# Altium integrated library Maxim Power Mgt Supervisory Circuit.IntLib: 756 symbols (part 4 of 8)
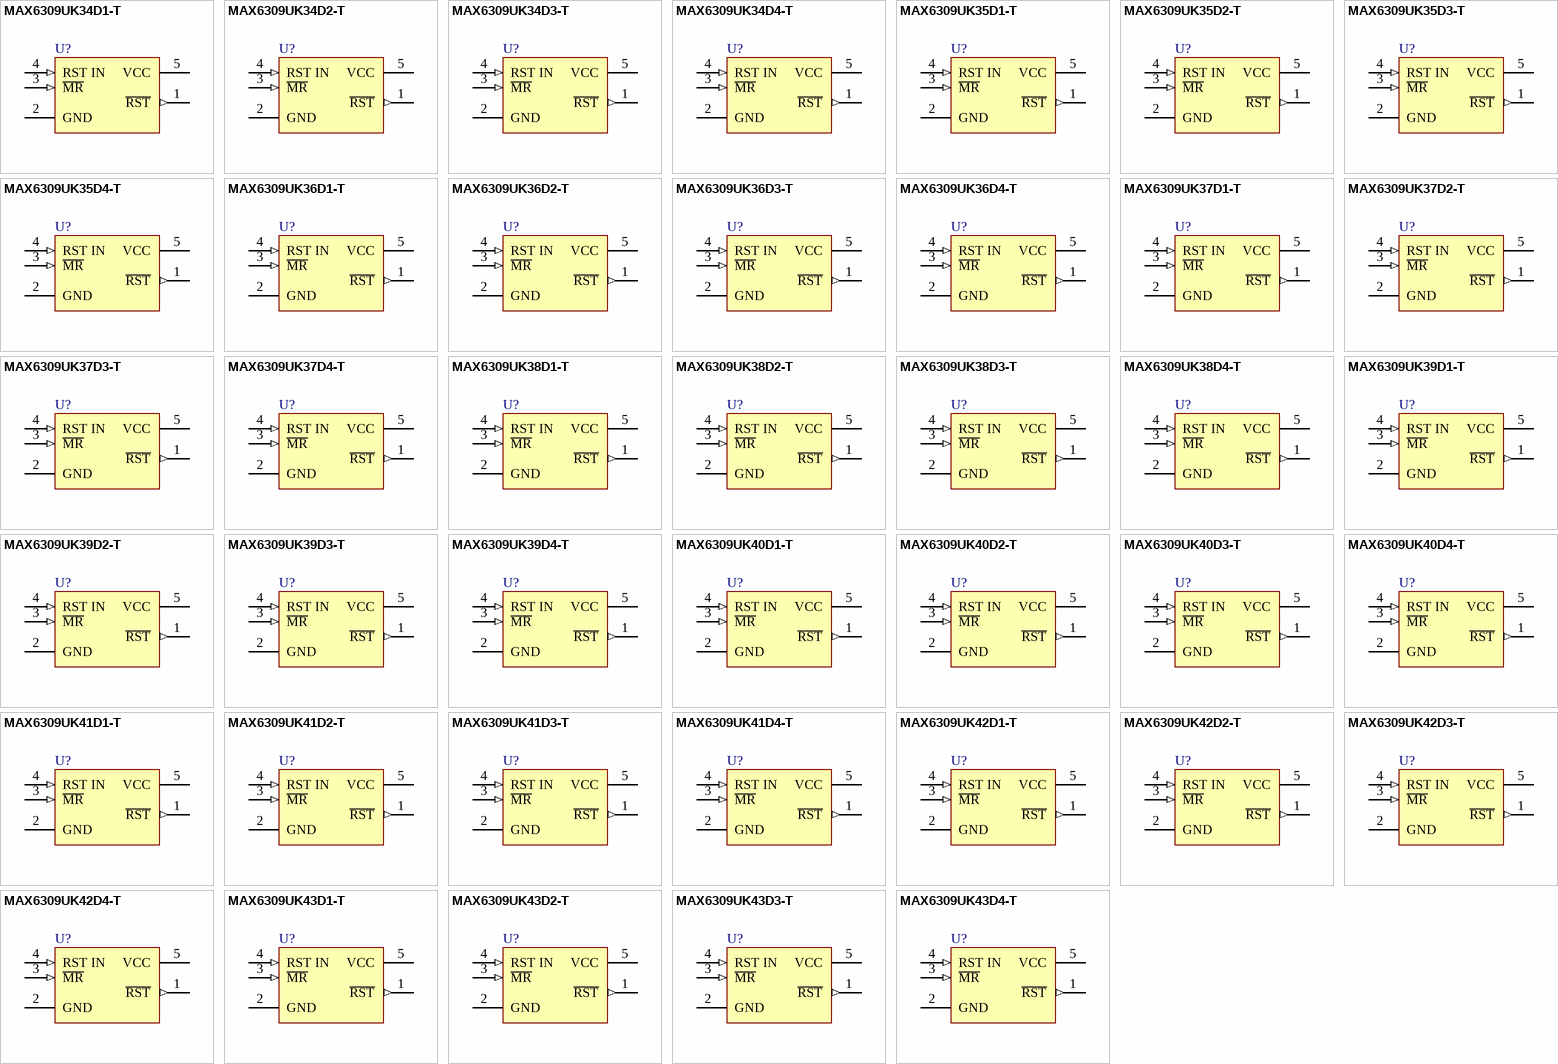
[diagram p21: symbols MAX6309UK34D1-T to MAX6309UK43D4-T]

## MAX6309UK35D2-T
designator U?
5-Pin, Multiple-Input, Programmable Reset IC
footprint SOT23-5_N (SOT23, 5-Leads, Body 2.9x1.6mm, Pitch 0.95mm, Lead Span 2.8mm, IPC Medium Density)
footprint SOT23-5_L (SOT23, 5-Leads, Body 2.9x1.6mm, Pitch 0.95mm, Lead Span 2.8mm, IPC High Density)
footprint SOT23-5_M (SOT23, 5-Leads, Body 2.9x1.6mm, Pitch 0.95mm, Lead Span 2.8mm, IPC Low Density)
pins: 1 ~{RST} (out), 2 GND (power), 3 ~{MR} (in), 4 RST IN (in), 5 VCC (power)

## MAX6309UK35D3-T
designator U?
5-Pin, Multiple-Input, Programmable Reset IC
footprint SOT23-5_N (SOT23, 5-Leads, Body 2.9x1.6mm, Pitch 0.95mm, Lead Span 2.8mm, IPC Medium Density)
footprint SOT23-5_L (SOT23, 5-Leads, Body 2.9x1.6mm, Pitch 0.95mm, Lead Span 2.8mm, IPC High Density)
footprint SOT23-5_M (SOT23, 5-Leads, Body 2.9x1.6mm, Pitch 0.95mm, Lead Span 2.8mm, IPC Low Density)
pins: 1 ~{RST} (out), 2 GND (power), 3 ~{MR} (in), 4 RST IN (in), 5 VCC (power)

## MAX6309UK35D4-T
designator U?
5-Pin, Multiple-Input, Programmable Reset IC
footprint SOT23-5_N (SOT23, 5-Leads, Body 2.9x1.6mm, Pitch 0.95mm, Lead Span 2.8mm, IPC Medium Density)
footprint SOT23-5_L (SOT23, 5-Leads, Body 2.9x1.6mm, Pitch 0.95mm, Lead Span 2.8mm, IPC High Density)
footprint SOT23-5_M (SOT23, 5-Leads, Body 2.9x1.6mm, Pitch 0.95mm, Lead Span 2.8mm, IPC Low Density)
pins: 1 ~{RST} (out), 2 GND (power), 3 ~{MR} (in), 4 RST IN (in), 5 VCC (power)

## MAX6309UK36D1-T
designator U?
5-Pin, Multiple-Input, Programmable Reset IC
footprint SOT23-5_N (SOT23, 5-Leads, Body 2.9x1.6mm, Pitch 0.95mm, Lead Span 2.8mm, IPC Medium Density)
footprint SOT23-5_L (SOT23, 5-Leads, Body 2.9x1.6mm, Pitch 0.95mm, Lead Span 2.8mm, IPC High Density)
footprint SOT23-5_M (SOT23, 5-Leads, Body 2.9x1.6mm, Pitch 0.95mm, Lead Span 2.8mm, IPC Low Density)
pins: 1 ~{RST} (out), 2 GND (power), 3 ~{MR} (in), 4 RST IN (in), 5 VCC (power)

## MAX6309UK36D2-T
designator U?
5-Pin, Multiple-Input, Programmable Reset IC
footprint SOT23-5_N (SOT23, 5-Leads, Body 2.9x1.6mm, Pitch 0.95mm, Lead Span 2.8mm, IPC Medium Density)
footprint SOT23-5_L (SOT23, 5-Leads, Body 2.9x1.6mm, Pitch 0.95mm, Lead Span 2.8mm, IPC High Density)
footprint SOT23-5_M (SOT23, 5-Leads, Body 2.9x1.6mm, Pitch 0.95mm, Lead Span 2.8mm, IPC Low Density)
pins: 1 ~{RST} (out), 2 GND (power), 3 ~{MR} (in), 4 RST IN (in), 5 VCC (power)

## MAX6309UK36D3-T
designator U?
5-Pin, Multiple-Input, Programmable Reset IC
footprint SOT23-5_N (SOT23, 5-Leads, Body 2.9x1.6mm, Pitch 0.95mm, Lead Span 2.8mm, IPC Medium Density)
footprint SOT23-5_L (SOT23, 5-Leads, Body 2.9x1.6mm, Pitch 0.95mm, Lead Span 2.8mm, IPC High Density)
footprint SOT23-5_M (SOT23, 5-Leads, Body 2.9x1.6mm, Pitch 0.95mm, Lead Span 2.8mm, IPC Low Density)
pins: 1 ~{RST} (out), 2 GND (power), 3 ~{MR} (in), 4 RST IN (in), 5 VCC (power)

## MAX6309UK36D4-T
designator U?
5-Pin, Multiple-Input, Programmable Reset IC
footprint SOT23-5_N (SOT23, 5-Leads, Body 2.9x1.6mm, Pitch 0.95mm, Lead Span 2.8mm, IPC Medium Density)
footprint SOT23-5_L (SOT23, 5-Leads, Body 2.9x1.6mm, Pitch 0.95mm, Lead Span 2.8mm, IPC High Density)
footprint SOT23-5_M (SOT23, 5-Leads, Body 2.9x1.6mm, Pitch 0.95mm, Lead Span 2.8mm, IPC Low Density)
pins: 1 ~{RST} (out), 2 GND (power), 3 ~{MR} (in), 4 RST IN (in), 5 VCC (power)

## MAX6309UK37D1-T
designator U?
5-Pin, Multiple-Input, Programmable Reset IC
footprint SOT23-5_N (SOT23, 5-Leads, Body 2.9x1.6mm, Pitch 0.95mm, Lead Span 2.8mm, IPC Medium Density)
footprint SOT23-5_L (SOT23, 5-Leads, Body 2.9x1.6mm, Pitch 0.95mm, Lead Span 2.8mm, IPC High Density)
footprint SOT23-5_M (SOT23, 5-Leads, Body 2.9x1.6mm, Pitch 0.95mm, Lead Span 2.8mm, IPC Low Density)
pins: 1 ~{RST} (out), 2 GND (power), 3 ~{MR} (in), 4 RST IN (in), 5 VCC (power)

## MAX6309UK37D2-T
designator U?
5-Pin, Multiple-Input, Programmable Reset IC
footprint SOT23-5_N (SOT23, 5-Leads, Body 2.9x1.6mm, Pitch 0.95mm, Lead Span 2.8mm, IPC Medium Density)
footprint SOT23-5_L (SOT23, 5-Leads, Body 2.9x1.6mm, Pitch 0.95mm, Lead Span 2.8mm, IPC High Density)
footprint SOT23-5_M (SOT23, 5-Leads, Body 2.9x1.6mm, Pitch 0.95mm, Lead Span 2.8mm, IPC Low Density)
pins: 1 ~{RST} (out), 2 GND (power), 3 ~{MR} (in), 4 RST IN (in), 5 VCC (power)

## MAX6309UK37D3-T
designator U?
5-Pin, Multiple-Input, Programmable Reset IC
footprint SOT23-5_N (SOT23, 5-Leads, Body 2.9x1.6mm, Pitch 0.95mm, Lead Span 2.8mm, IPC Medium Density)
footprint SOT23-5_L (SOT23, 5-Leads, Body 2.9x1.6mm, Pitch 0.95mm, Lead Span 2.8mm, IPC High Density)
footprint SOT23-5_M (SOT23, 5-Leads, Body 2.9x1.6mm, Pitch 0.95mm, Lead Span 2.8mm, IPC Low Density)
pins: 1 ~{RST} (out), 2 GND (power), 3 ~{MR} (in), 4 RST IN (in), 5 VCC (power)

## MAX6309UK37D4-T
designator U?
5-Pin, Multiple-Input, Programmable Reset IC
footprint SOT23-5_N (SOT23, 5-Leads, Body 2.9x1.6mm, Pitch 0.95mm, Lead Span 2.8mm, IPC Medium Density)
footprint SOT23-5_L (SOT23, 5-Leads, Body 2.9x1.6mm, Pitch 0.95mm, Lead Span 2.8mm, IPC High Density)
footprint SOT23-5_M (SOT23, 5-Leads, Body 2.9x1.6mm, Pitch 0.95mm, Lead Span 2.8mm, IPC Low Density)
pins: 1 ~{RST} (out), 2 GND (power), 3 ~{MR} (in), 4 RST IN (in), 5 VCC (power)

## MAX6309UK38D1-T
designator U?
5-Pin, Multiple-Input, Programmable Reset IC
footprint SOT23-5_N (SOT23, 5-Leads, Body 2.9x1.6mm, Pitch 0.95mm, Lead Span 2.8mm, IPC Medium Density)
footprint SOT23-5_L (SOT23, 5-Leads, Body 2.9x1.6mm, Pitch 0.95mm, Lead Span 2.8mm, IPC High Density)
footprint SOT23-5_M (SOT23, 5-Leads, Body 2.9x1.6mm, Pitch 0.95mm, Lead Span 2.8mm, IPC Low Density)
pins: 1 ~{RST} (out), 2 GND (power), 3 ~{MR} (in), 4 RST IN (in), 5 VCC (power)

## MAX6309UK38D2-T
designator U?
5-Pin, Multiple-Input, Programmable Reset IC
footprint SOT23-5_N (SOT23, 5-Leads, Body 2.9x1.6mm, Pitch 0.95mm, Lead Span 2.8mm, IPC Medium Density)
footprint SOT23-5_L (SOT23, 5-Leads, Body 2.9x1.6mm, Pitch 0.95mm, Lead Span 2.8mm, IPC High Density)
footprint SOT23-5_M (SOT23, 5-Leads, Body 2.9x1.6mm, Pitch 0.95mm, Lead Span 2.8mm, IPC Low Density)
pins: 1 ~{RST} (out), 2 GND (power), 3 ~{MR} (in), 4 RST IN (in), 5 VCC (power)

## MAX6309UK38D3-T
designator U?
5-Pin, Multiple-Input, Programmable Reset IC
footprint SOT23-5_N (SOT23, 5-Leads, Body 2.9x1.6mm, Pitch 0.95mm, Lead Span 2.8mm, IPC Medium Density)
footprint SOT23-5_L (SOT23, 5-Leads, Body 2.9x1.6mm, Pitch 0.95mm, Lead Span 2.8mm, IPC High Density)
footprint SOT23-5_M (SOT23, 5-Leads, Body 2.9x1.6mm, Pitch 0.95mm, Lead Span 2.8mm, IPC Low Density)
pins: 1 ~{RST} (out), 2 GND (power), 3 ~{MR} (in), 4 RST IN (in), 5 VCC (power)

## MAX6309UK38D4-T
designator U?
5-Pin, Multiple-Input, Programmable Reset IC
footprint SOT23-5_N (SOT23, 5-Leads, Body 2.9x1.6mm, Pitch 0.95mm, Lead Span 2.8mm, IPC Medium Density)
footprint SOT23-5_L (SOT23, 5-Leads, Body 2.9x1.6mm, Pitch 0.95mm, Lead Span 2.8mm, IPC High Density)
footprint SOT23-5_M (SOT23, 5-Leads, Body 2.9x1.6mm, Pitch 0.95mm, Lead Span 2.8mm, IPC Low Density)
pins: 1 ~{RST} (out), 2 GND (power), 3 ~{MR} (in), 4 RST IN (in), 5 VCC (power)

## MAX6309UK39D1-T
designator U?
5-Pin, Multiple-Input, Programmable Reset IC
footprint SOT23-5_N (SOT23, 5-Leads, Body 2.9x1.6mm, Pitch 0.95mm, Lead Span 2.8mm, IPC Medium Density)
footprint SOT23-5_L (SOT23, 5-Leads, Body 2.9x1.6mm, Pitch 0.95mm, Lead Span 2.8mm, IPC High Density)
footprint SOT23-5_M (SOT23, 5-Leads, Body 2.9x1.6mm, Pitch 0.95mm, Lead Span 2.8mm, IPC Low Density)
pins: 1 ~{RST} (out), 2 GND (power), 3 ~{MR} (in), 4 RST IN (in), 5 VCC (power)

## MAX6309UK39D2-T
designator U?
5-Pin, Multiple-Input, Programmable Reset IC
footprint SOT23-5_N (SOT23, 5-Leads, Body 2.9x1.6mm, Pitch 0.95mm, Lead Span 2.8mm, IPC Medium Density)
footprint SOT23-5_L (SOT23, 5-Leads, Body 2.9x1.6mm, Pitch 0.95mm, Lead Span 2.8mm, IPC High Density)
footprint SOT23-5_M (SOT23, 5-Leads, Body 2.9x1.6mm, Pitch 0.95mm, Lead Span 2.8mm, IPC Low Density)
pins: 1 ~{RST} (out), 2 GND (power), 3 ~{MR} (in), 4 RST IN (in), 5 VCC (power)

## MAX6309UK39D3-T
designator U?
5-Pin, Multiple-Input, Programmable Reset IC
footprint SOT23-5_N (SOT23, 5-Leads, Body 2.9x1.6mm, Pitch 0.95mm, Lead Span 2.8mm, IPC Medium Density)
footprint SOT23-5_L (SOT23, 5-Leads, Body 2.9x1.6mm, Pitch 0.95mm, Lead Span 2.8mm, IPC High Density)
footprint SOT23-5_M (SOT23, 5-Leads, Body 2.9x1.6mm, Pitch 0.95mm, Lead Span 2.8mm, IPC Low Density)
pins: 1 ~{RST} (out), 2 GND (power), 3 ~{MR} (in), 4 RST IN (in), 5 VCC (power)

## MAX6309UK39D4-T
designator U?
5-Pin, Multiple-Input, Programmable Reset IC
footprint SOT23-5_N (SOT23, 5-Leads, Body 2.9x1.6mm, Pitch 0.95mm, Lead Span 2.8mm, IPC Medium Density)
footprint SOT23-5_L (SOT23, 5-Leads, Body 2.9x1.6mm, Pitch 0.95mm, Lead Span 2.8mm, IPC High Density)
footprint SOT23-5_M (SOT23, 5-Leads, Body 2.9x1.6mm, Pitch 0.95mm, Lead Span 2.8mm, IPC Low Density)
pins: 1 ~{RST} (out), 2 GND (power), 3 ~{MR} (in), 4 RST IN (in), 5 VCC (power)

## MAX6309UK40D1-T
designator U?
5-Pin, Multiple-Input, Programmable Reset IC
footprint SOT23-5_N (SOT23, 5-Leads, Body 2.9x1.6mm, Pitch 0.95mm, Lead Span 2.8mm, IPC Medium Density)
footprint SOT23-5_L (SOT23, 5-Leads, Body 2.9x1.6mm, Pitch 0.95mm, Lead Span 2.8mm, IPC High Density)
footprint SOT23-5_M (SOT23, 5-Leads, Body 2.9x1.6mm, Pitch 0.95mm, Lead Span 2.8mm, IPC Low Density)
pins: 1 ~{RST} (out), 2 GND (power), 3 ~{MR} (in), 4 RST IN (in), 5 VCC (power)

## MAX6309UK40D2-T
designator U?
5-Pin, Multiple-Input, Programmable Reset IC
footprint SOT23-5_N (SOT23, 5-Leads, Body 2.9x1.6mm, Pitch 0.95mm, Lead Span 2.8mm, IPC Medium Density)
footprint SOT23-5_L (SOT23, 5-Leads, Body 2.9x1.6mm, Pitch 0.95mm, Lead Span 2.8mm, IPC High Density)
footprint SOT23-5_M (SOT23, 5-Leads, Body 2.9x1.6mm, Pitch 0.95mm, Lead Span 2.8mm, IPC Low Density)
pins: 1 ~{RST} (out), 2 GND (power), 3 ~{MR} (in), 4 RST IN (in), 5 VCC (power)

## MAX6309UK40D3-T
designator U?
5-Pin, Multiple-Input, Programmable Reset IC
footprint SOT23-5_N (SOT23, 5-Leads, Body 2.9x1.6mm, Pitch 0.95mm, Lead Span 2.8mm, IPC Medium Density)
footprint SOT23-5_L (SOT23, 5-Leads, Body 2.9x1.6mm, Pitch 0.95mm, Lead Span 2.8mm, IPC High Density)
footprint SOT23-5_M (SOT23, 5-Leads, Body 2.9x1.6mm, Pitch 0.95mm, Lead Span 2.8mm, IPC Low Density)
pins: 1 ~{RST} (out), 2 GND (power), 3 ~{MR} (in), 4 RST IN (in), 5 VCC (power)

## MAX6309UK40D4-T
designator U?
5-Pin, Multiple-Input, Programmable Reset IC
footprint SOT23-5_N (SOT23, 5-Leads, Body 2.9x1.6mm, Pitch 0.95mm, Lead Span 2.8mm, IPC Medium Density)
footprint SOT23-5_L (SOT23, 5-Leads, Body 2.9x1.6mm, Pitch 0.95mm, Lead Span 2.8mm, IPC High Density)
footprint SOT23-5_M (SOT23, 5-Leads, Body 2.9x1.6mm, Pitch 0.95mm, Lead Span 2.8mm, IPC Low Density)
pins: 1 ~{RST} (out), 2 GND (power), 3 ~{MR} (in), 4 RST IN (in), 5 VCC (power)

## MAX6309UK41D1-T
designator U?
5-Pin, Multiple-Input, Programmable Reset IC
footprint SOT23-5_N (SOT23, 5-Leads, Body 2.9x1.6mm, Pitch 0.95mm, Lead Span 2.8mm, IPC Medium Density)
footprint SOT23-5_L (SOT23, 5-Leads, Body 2.9x1.6mm, Pitch 0.95mm, Lead Span 2.8mm, IPC High Density)
footprint SOT23-5_M (SOT23, 5-Leads, Body 2.9x1.6mm, Pitch 0.95mm, Lead Span 2.8mm, IPC Low Density)
pins: 1 ~{RST} (out), 2 GND (power), 3 ~{MR} (in), 4 RST IN (in), 5 VCC (power)

## MAX6309UK41D2-T
designator U?
5-Pin, Multiple-Input, Programmable Reset IC
footprint SOT23-5_N (SOT23, 5-Leads, Body 2.9x1.6mm, Pitch 0.95mm, Lead Span 2.8mm, IPC Medium Density)
footprint SOT23-5_L (SOT23, 5-Leads, Body 2.9x1.6mm, Pitch 0.95mm, Lead Span 2.8mm, IPC High Density)
footprint SOT23-5_M (SOT23, 5-Leads, Body 2.9x1.6mm, Pitch 0.95mm, Lead Span 2.8mm, IPC Low Density)
pins: 1 ~{RST} (out), 2 GND (power), 3 ~{MR} (in), 4 RST IN (in), 5 VCC (power)

## MAX6309UK41D3-T
designator U?
5-Pin, Multiple-Input, Programmable Reset IC
footprint SOT23-5_N (SOT23, 5-Leads, Body 2.9x1.6mm, Pitch 0.95mm, Lead Span 2.8mm, IPC Medium Density)
footprint SOT23-5_L (SOT23, 5-Leads, Body 2.9x1.6mm, Pitch 0.95mm, Lead Span 2.8mm, IPC High Density)
footprint SOT23-5_M (SOT23, 5-Leads, Body 2.9x1.6mm, Pitch 0.95mm, Lead Span 2.8mm, IPC Low Density)
pins: 1 ~{RST} (out), 2 GND (power), 3 ~{MR} (in), 4 RST IN (in), 5 VCC (power)

## MAX6309UK41D4-T
designator U?
5-Pin, Multiple-Input, Programmable Reset IC
footprint SOT23-5_N (SOT23, 5-Leads, Body 2.9x1.6mm, Pitch 0.95mm, Lead Span 2.8mm, IPC Medium Density)
footprint SOT23-5_L (SOT23, 5-Leads, Body 2.9x1.6mm, Pitch 0.95mm, Lead Span 2.8mm, IPC High Density)
footprint SOT23-5_M (SOT23, 5-Leads, Body 2.9x1.6mm, Pitch 0.95mm, Lead Span 2.8mm, IPC Low Density)
pins: 1 ~{RST} (out), 2 GND (power), 3 ~{MR} (in), 4 RST IN (in), 5 VCC (power)

## MAX6309UK42D1-T
designator U?
5-Pin, Multiple-Input, Programmable Reset IC
footprint SOT23-5_N (SOT23, 5-Leads, Body 2.9x1.6mm, Pitch 0.95mm, Lead Span 2.8mm, IPC Medium Density)
footprint SOT23-5_L (SOT23, 5-Leads, Body 2.9x1.6mm, Pitch 0.95mm, Lead Span 2.8mm, IPC High Density)
footprint SOT23-5_M (SOT23, 5-Leads, Body 2.9x1.6mm, Pitch 0.95mm, Lead Span 2.8mm, IPC Low Density)
pins: 1 ~{RST} (out), 2 GND (power), 3 ~{MR} (in), 4 RST IN (in), 5 VCC (power)

## MAX6309UK42D2-T
designator U?
5-Pin, Multiple-Input, Programmable Reset IC
footprint SOT23-5_N (SOT23, 5-Leads, Body 2.9x1.6mm, Pitch 0.95mm, Lead Span 2.8mm, IPC Medium Density)
footprint SOT23-5_L (SOT23, 5-Leads, Body 2.9x1.6mm, Pitch 0.95mm, Lead Span 2.8mm, IPC High Density)
footprint SOT23-5_M (SOT23, 5-Leads, Body 2.9x1.6mm, Pitch 0.95mm, Lead Span 2.8mm, IPC Low Density)
pins: 1 ~{RST} (out), 2 GND (power), 3 ~{MR} (in), 4 RST IN (in), 5 VCC (power)

## MAX6309UK42D3-T
designator U?
5-Pin, Multiple-Input, Programmable Reset IC
footprint SOT23-5_N (SOT23, 5-Leads, Body 2.9x1.6mm, Pitch 0.95mm, Lead Span 2.8mm, IPC Medium Density)
footprint SOT23-5_L (SOT23, 5-Leads, Body 2.9x1.6mm, Pitch 0.95mm, Lead Span 2.8mm, IPC High Density)
footprint SOT23-5_M (SOT23, 5-Leads, Body 2.9x1.6mm, Pitch 0.95mm, Lead Span 2.8mm, IPC Low Density)
pins: 1 ~{RST} (out), 2 GND (power), 3 ~{MR} (in), 4 RST IN (in), 5 VCC (power)

## MAX6309UK42D4-T
designator U?
5-Pin, Multiple-Input, Programmable Reset IC
footprint SOT23-5_N (SOT23, 5-Leads, Body 2.9x1.6mm, Pitch 0.95mm, Lead Span 2.8mm, IPC Medium Density)
footprint SOT23-5_L (SOT23, 5-Leads, Body 2.9x1.6mm, Pitch 0.95mm, Lead Span 2.8mm, IPC High Density)
footprint SOT23-5_M (SOT23, 5-Leads, Body 2.9x1.6mm, Pitch 0.95mm, Lead Span 2.8mm, IPC Low Density)
pins: 1 ~{RST} (out), 2 GND (power), 3 ~{MR} (in), 4 RST IN (in), 5 VCC (power)

## MAX6309UK43D1-T
designator U?
5-Pin, Multiple-Input, Programmable Reset IC
footprint SOT23-5_N (SOT23, 5-Leads, Body 2.9x1.6mm, Pitch 0.95mm, Lead Span 2.8mm, IPC Medium Density)
footprint SOT23-5_L (SOT23, 5-Leads, Body 2.9x1.6mm, Pitch 0.95mm, Lead Span 2.8mm, IPC High Density)
footprint SOT23-5_M (SOT23, 5-Leads, Body 2.9x1.6mm, Pitch 0.95mm, Lead Span 2.8mm, IPC Low Density)
pins: 1 ~{RST} (out), 2 GND (power), 3 ~{MR} (in), 4 RST IN (in), 5 VCC (power)

## MAX6309UK43D2-T
designator U?
5-Pin, Multiple-Input, Programmable Reset IC
footprint SOT23-5_N (SOT23, 5-Leads, Body 2.9x1.6mm, Pitch 0.95mm, Lead Span 2.8mm, IPC Medium Density)
footprint SOT23-5_L (SOT23, 5-Leads, Body 2.9x1.6mm, Pitch 0.95mm, Lead Span 2.8mm, IPC High Density)
footprint SOT23-5_M (SOT23, 5-Leads, Body 2.9x1.6mm, Pitch 0.95mm, Lead Span 2.8mm, IPC Low Density)
pins: 1 ~{RST} (out), 2 GND (power), 3 ~{MR} (in), 4 RST IN (in), 5 VCC (power)

## MAX6309UK43D3-T
designator U?
5-Pin, Multiple-Input, Programmable Reset IC
footprint SOT23-5_N (SOT23, 5-Leads, Body 2.9x1.6mm, Pitch 0.95mm, Lead Span 2.8mm, IPC Medium Density)
footprint SOT23-5_L (SOT23, 5-Leads, Body 2.9x1.6mm, Pitch 0.95mm, Lead Span 2.8mm, IPC High Density)
footprint SOT23-5_M (SOT23, 5-Leads, Body 2.9x1.6mm, Pitch 0.95mm, Lead Span 2.8mm, IPC Low Density)
pins: 1 ~{RST} (out), 2 GND (power), 3 ~{MR} (in), 4 RST IN (in), 5 VCC (power)

## MAX6309UK43D4-T
designator U?
5-Pin, Multiple-Input, Programmable Reset IC
footprint SOT23-5_N (SOT23, 5-Leads, Body 2.9x1.6mm, Pitch 0.95mm, Lead Span 2.8mm, IPC Medium Density)
footprint SOT23-5_L (SOT23, 5-Leads, Body 2.9x1.6mm, Pitch 0.95mm, Lead Span 2.8mm, IPC High Density)
footprint SOT23-5_M (SOT23, 5-Leads, Body 2.9x1.6mm, Pitch 0.95mm, Lead Span 2.8mm, IPC Low Density)
pins: 1 ~{RST} (out), 2 GND (power), 3 ~{MR} (in), 4 RST IN (in), 5 VCC (power)

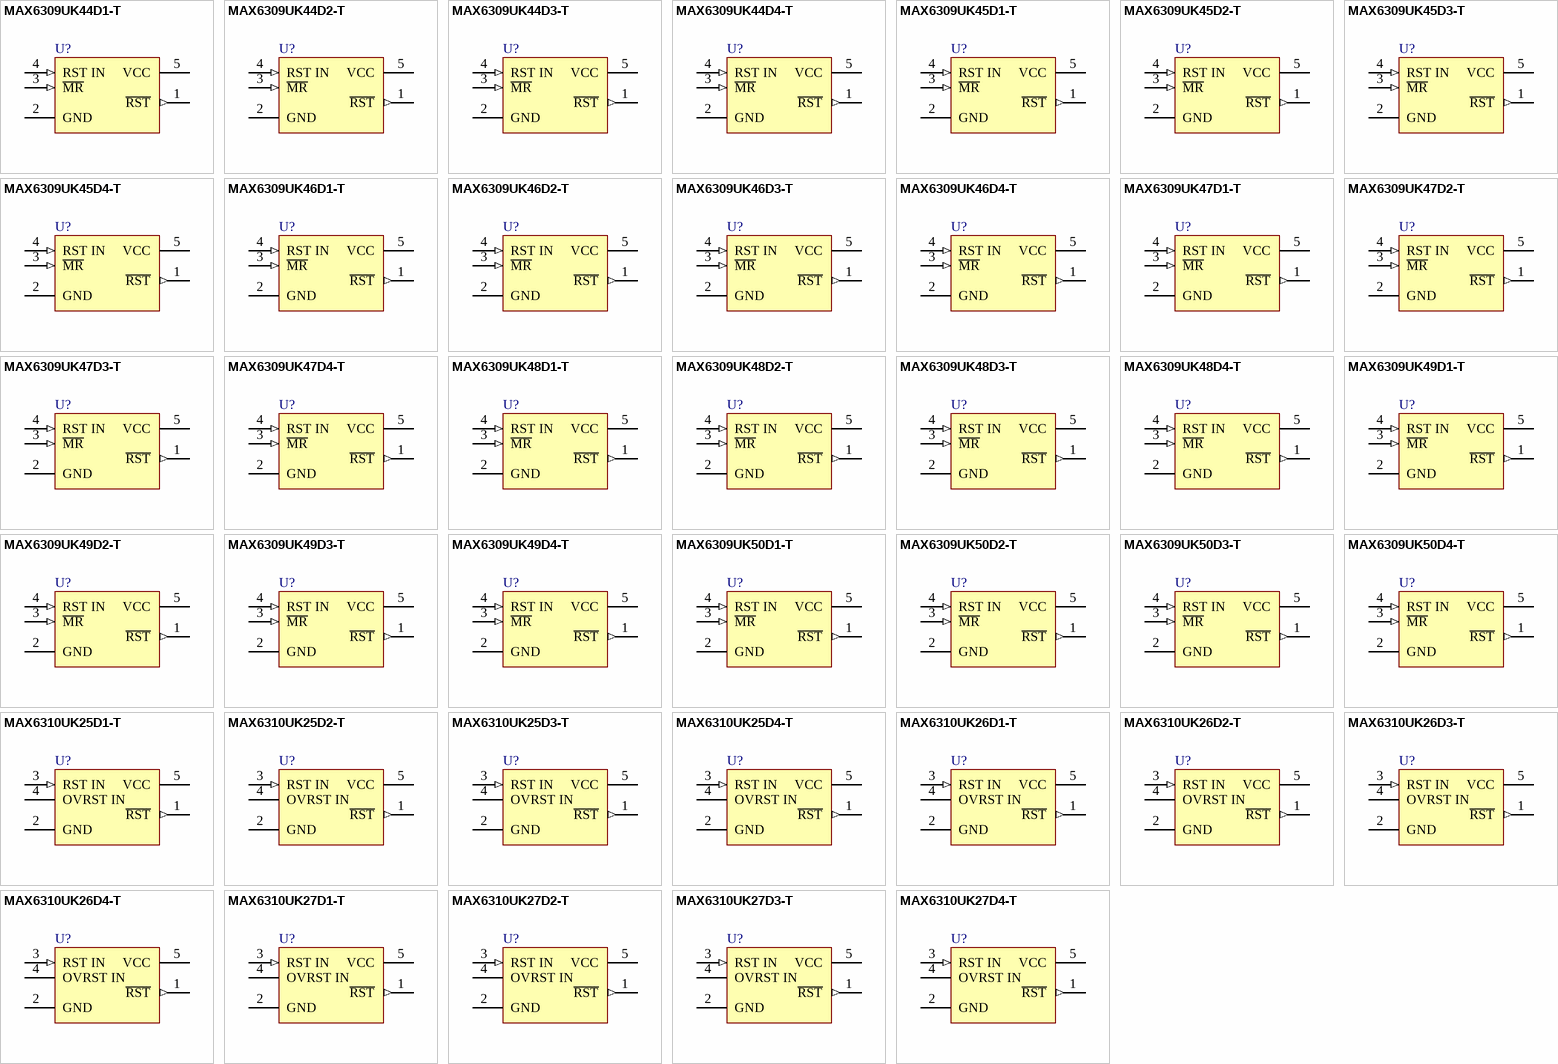
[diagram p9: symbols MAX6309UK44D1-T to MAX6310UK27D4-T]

## MAX6309UK44D1-T
designator U?
5-Pin, Multiple-Input, Programmable Reset IC
footprint SOT23-5_N (SOT23, 5-Leads, Body 2.9x1.6mm, Pitch 0.95mm, Lead Span 2.8mm, IPC Medium Density)
footprint SOT23-5_L (SOT23, 5-Leads, Body 2.9x1.6mm, Pitch 0.95mm, Lead Span 2.8mm, IPC High Density)
footprint SOT23-5_M (SOT23, 5-Leads, Body 2.9x1.6mm, Pitch 0.95mm, Lead Span 2.8mm, IPC Low Density)
pins: 1 ~{RST} (out), 2 GND (power), 3 ~{MR} (in), 4 RST IN (in), 5 VCC (power)

## MAX6309UK44D2-T
designator U?
5-Pin, Multiple-Input, Programmable Reset IC
footprint SOT23-5_N (SOT23, 5-Leads, Body 2.9x1.6mm, Pitch 0.95mm, Lead Span 2.8mm, IPC Medium Density)
footprint SOT23-5_L (SOT23, 5-Leads, Body 2.9x1.6mm, Pitch 0.95mm, Lead Span 2.8mm, IPC High Density)
footprint SOT23-5_M (SOT23, 5-Leads, Body 2.9x1.6mm, Pitch 0.95mm, Lead Span 2.8mm, IPC Low Density)
pins: 1 ~{RST} (out), 2 GND (power), 3 ~{MR} (in), 4 RST IN (in), 5 VCC (power)

## MAX6309UK44D3-T
designator U?
5-Pin, Multiple-Input, Programmable Reset IC
footprint SOT23-5_N (SOT23, 5-Leads, Body 2.9x1.6mm, Pitch 0.95mm, Lead Span 2.8mm, IPC Medium Density)
footprint SOT23-5_L (SOT23, 5-Leads, Body 2.9x1.6mm, Pitch 0.95mm, Lead Span 2.8mm, IPC High Density)
footprint SOT23-5_M (SOT23, 5-Leads, Body 2.9x1.6mm, Pitch 0.95mm, Lead Span 2.8mm, IPC Low Density)
pins: 1 ~{RST} (out), 2 GND (power), 3 ~{MR} (in), 4 RST IN (in), 5 VCC (power)

## MAX6309UK44D4-T
designator U?
5-Pin, Multiple-Input, Programmable Reset IC
footprint SOT23-5_N (SOT23, 5-Leads, Body 2.9x1.6mm, Pitch 0.95mm, Lead Span 2.8mm, IPC Medium Density)
footprint SOT23-5_L (SOT23, 5-Leads, Body 2.9x1.6mm, Pitch 0.95mm, Lead Span 2.8mm, IPC High Density)
footprint SOT23-5_M (SOT23, 5-Leads, Body 2.9x1.6mm, Pitch 0.95mm, Lead Span 2.8mm, IPC Low Density)
pins: 1 ~{RST} (out), 2 GND (power), 3 ~{MR} (in), 4 RST IN (in), 5 VCC (power)

## MAX6309UK45D1-T
designator U?
5-Pin, Multiple-Input, Programmable Reset IC
footprint SOT23-5_N (SOT23, 5-Leads, Body 2.9x1.6mm, Pitch 0.95mm, Lead Span 2.8mm, IPC Medium Density)
footprint SOT23-5_L (SOT23, 5-Leads, Body 2.9x1.6mm, Pitch 0.95mm, Lead Span 2.8mm, IPC High Density)
footprint SOT23-5_M (SOT23, 5-Leads, Body 2.9x1.6mm, Pitch 0.95mm, Lead Span 2.8mm, IPC Low Density)
pins: 1 ~{RST} (out), 2 GND (power), 3 ~{MR} (in), 4 RST IN (in), 5 VCC (power)

## MAX6309UK45D2-T
designator U?
5-Pin, Multiple-Input, Programmable Reset IC
footprint SOT23-5_N (SOT23, 5-Leads, Body 2.9x1.6mm, Pitch 0.95mm, Lead Span 2.8mm, IPC Medium Density)
footprint SOT23-5_L (SOT23, 5-Leads, Body 2.9x1.6mm, Pitch 0.95mm, Lead Span 2.8mm, IPC High Density)
footprint SOT23-5_M (SOT23, 5-Leads, Body 2.9x1.6mm, Pitch 0.95mm, Lead Span 2.8mm, IPC Low Density)
pins: 1 ~{RST} (out), 2 GND (power), 3 ~{MR} (in), 4 RST IN (in), 5 VCC (power)

## MAX6309UK45D3-T
designator U?
5-Pin, Multiple-Input, Programmable Reset IC
footprint SOT23-5_N (SOT23, 5-Leads, Body 2.9x1.6mm, Pitch 0.95mm, Lead Span 2.8mm, IPC Medium Density)
footprint SOT23-5_L (SOT23, 5-Leads, Body 2.9x1.6mm, Pitch 0.95mm, Lead Span 2.8mm, IPC High Density)
footprint SOT23-5_M (SOT23, 5-Leads, Body 2.9x1.6mm, Pitch 0.95mm, Lead Span 2.8mm, IPC Low Density)
pins: 1 ~{RST} (out), 2 GND (power), 3 ~{MR} (in), 4 RST IN (in), 5 VCC (power)

## MAX6309UK45D4-T
designator U?
5-Pin, Multiple-Input, Programmable Reset IC
footprint SOT23-5_N (SOT23, 5-Leads, Body 2.9x1.6mm, Pitch 0.95mm, Lead Span 2.8mm, IPC Medium Density)
footprint SOT23-5_L (SOT23, 5-Leads, Body 2.9x1.6mm, Pitch 0.95mm, Lead Span 2.8mm, IPC High Density)
footprint SOT23-5_M (SOT23, 5-Leads, Body 2.9x1.6mm, Pitch 0.95mm, Lead Span 2.8mm, IPC Low Density)
pins: 1 ~{RST} (out), 2 GND (power), 3 ~{MR} (in), 4 RST IN (in), 5 VCC (power)

## MAX6309UK46D1-T
designator U?
5-Pin, Multiple-Input, Programmable Reset IC
footprint SOT23-5_N (SOT23, 5-Leads, Body 2.9x1.6mm, Pitch 0.95mm, Lead Span 2.8mm, IPC Medium Density)
footprint SOT23-5_L (SOT23, 5-Leads, Body 2.9x1.6mm, Pitch 0.95mm, Lead Span 2.8mm, IPC High Density)
footprint SOT23-5_M (SOT23, 5-Leads, Body 2.9x1.6mm, Pitch 0.95mm, Lead Span 2.8mm, IPC Low Density)
pins: 1 ~{RST} (out), 2 GND (power), 3 ~{MR} (in), 4 RST IN (in), 5 VCC (power)

## MAX6309UK46D2-T
designator U?
5-Pin, Multiple-Input, Programmable Reset IC
footprint SOT23-5_N (SOT23, 5-Leads, Body 2.9x1.6mm, Pitch 0.95mm, Lead Span 2.8mm, IPC Medium Density)
footprint SOT23-5_L (SOT23, 5-Leads, Body 2.9x1.6mm, Pitch 0.95mm, Lead Span 2.8mm, IPC High Density)
footprint SOT23-5_M (SOT23, 5-Leads, Body 2.9x1.6mm, Pitch 0.95mm, Lead Span 2.8mm, IPC Low Density)
pins: 1 ~{RST} (out), 2 GND (power), 3 ~{MR} (in), 4 RST IN (in), 5 VCC (power)

## MAX6309UK46D3-T
designator U?
5-Pin, Multiple-Input, Programmable Reset IC
footprint SOT23-5_N (SOT23, 5-Leads, Body 2.9x1.6mm, Pitch 0.95mm, Lead Span 2.8mm, IPC Medium Density)
footprint SOT23-5_L (SOT23, 5-Leads, Body 2.9x1.6mm, Pitch 0.95mm, Lead Span 2.8mm, IPC High Density)
footprint SOT23-5_M (SOT23, 5-Leads, Body 2.9x1.6mm, Pitch 0.95mm, Lead Span 2.8mm, IPC Low Density)
pins: 1 ~{RST} (out), 2 GND (power), 3 ~{MR} (in), 4 RST IN (in), 5 VCC (power)

## MAX6309UK46D4-T
designator U?
5-Pin, Multiple-Input, Programmable Reset IC
footprint SOT23-5_N (SOT23, 5-Leads, Body 2.9x1.6mm, Pitch 0.95mm, Lead Span 2.8mm, IPC Medium Density)
footprint SOT23-5_L (SOT23, 5-Leads, Body 2.9x1.6mm, Pitch 0.95mm, Lead Span 2.8mm, IPC High Density)
footprint SOT23-5_M (SOT23, 5-Leads, Body 2.9x1.6mm, Pitch 0.95mm, Lead Span 2.8mm, IPC Low Density)
pins: 1 ~{RST} (out), 2 GND (power), 3 ~{MR} (in), 4 RST IN (in), 5 VCC (power)

## MAX6309UK47D1-T
designator U?
5-Pin, Multiple-Input, Programmable Reset IC
footprint SOT23-5_N (SOT23, 5-Leads, Body 2.9x1.6mm, Pitch 0.95mm, Lead Span 2.8mm, IPC Medium Density)
footprint SOT23-5_L (SOT23, 5-Leads, Body 2.9x1.6mm, Pitch 0.95mm, Lead Span 2.8mm, IPC High Density)
footprint SOT23-5_M (SOT23, 5-Leads, Body 2.9x1.6mm, Pitch 0.95mm, Lead Span 2.8mm, IPC Low Density)
pins: 1 ~{RST} (out), 2 GND (power), 3 ~{MR} (in), 4 RST IN (in), 5 VCC (power)

## MAX6309UK47D2-T
designator U?
5-Pin, Multiple-Input, Programmable Reset IC
footprint SOT23-5_N (SOT23, 5-Leads, Body 2.9x1.6mm, Pitch 0.95mm, Lead Span 2.8mm, IPC Medium Density)
footprint SOT23-5_L (SOT23, 5-Leads, Body 2.9x1.6mm, Pitch 0.95mm, Lead Span 2.8mm, IPC High Density)
footprint SOT23-5_M (SOT23, 5-Leads, Body 2.9x1.6mm, Pitch 0.95mm, Lead Span 2.8mm, IPC Low Density)
pins: 1 ~{RST} (out), 2 GND (power), 3 ~{MR} (in), 4 RST IN (in), 5 VCC (power)

## MAX6309UK47D3-T
designator U?
5-Pin, Multiple-Input, Programmable Reset IC
footprint SOT23-5_N (SOT23, 5-Leads, Body 2.9x1.6mm, Pitch 0.95mm, Lead Span 2.8mm, IPC Medium Density)
footprint SOT23-5_L (SOT23, 5-Leads, Body 2.9x1.6mm, Pitch 0.95mm, Lead Span 2.8mm, IPC High Density)
footprint SOT23-5_M (SOT23, 5-Leads, Body 2.9x1.6mm, Pitch 0.95mm, Lead Span 2.8mm, IPC Low Density)
pins: 1 ~{RST} (out), 2 GND (power), 3 ~{MR} (in), 4 RST IN (in), 5 VCC (power)

## MAX6309UK47D4-T
designator U?
5-Pin, Multiple-Input, Programmable Reset IC
footprint SOT23-5_N (SOT23, 5-Leads, Body 2.9x1.6mm, Pitch 0.95mm, Lead Span 2.8mm, IPC Medium Density)
footprint SOT23-5_L (SOT23, 5-Leads, Body 2.9x1.6mm, Pitch 0.95mm, Lead Span 2.8mm, IPC High Density)
footprint SOT23-5_M (SOT23, 5-Leads, Body 2.9x1.6mm, Pitch 0.95mm, Lead Span 2.8mm, IPC Low Density)
pins: 1 ~{RST} (out), 2 GND (power), 3 ~{MR} (in), 4 RST IN (in), 5 VCC (power)

## MAX6309UK48D1-T
designator U?
5-Pin, Multiple-Input, Programmable Reset IC
footprint SOT23-5_N (SOT23, 5-Leads, Body 2.9x1.6mm, Pitch 0.95mm, Lead Span 2.8mm, IPC Medium Density)
footprint SOT23-5_L (SOT23, 5-Leads, Body 2.9x1.6mm, Pitch 0.95mm, Lead Span 2.8mm, IPC High Density)
footprint SOT23-5_M (SOT23, 5-Leads, Body 2.9x1.6mm, Pitch 0.95mm, Lead Span 2.8mm, IPC Low Density)
pins: 1 ~{RST} (out), 2 GND (power), 3 ~{MR} (in), 4 RST IN (in), 5 VCC (power)

## MAX6309UK48D2-T
designator U?
5-Pin, Multiple-Input, Programmable Reset IC
footprint SOT23-5_N (SOT23, 5-Leads, Body 2.9x1.6mm, Pitch 0.95mm, Lead Span 2.8mm, IPC Medium Density)
footprint SOT23-5_L (SOT23, 5-Leads, Body 2.9x1.6mm, Pitch 0.95mm, Lead Span 2.8mm, IPC High Density)
footprint SOT23-5_M (SOT23, 5-Leads, Body 2.9x1.6mm, Pitch 0.95mm, Lead Span 2.8mm, IPC Low Density)
pins: 1 ~{RST} (out), 2 GND (power), 3 ~{MR} (in), 4 RST IN (in), 5 VCC (power)

## MAX6309UK48D3-T
designator U?
5-Pin, Multiple-Input, Programmable Reset IC
footprint SOT23-5_N (SOT23, 5-Leads, Body 2.9x1.6mm, Pitch 0.95mm, Lead Span 2.8mm, IPC Medium Density)
footprint SOT23-5_L (SOT23, 5-Leads, Body 2.9x1.6mm, Pitch 0.95mm, Lead Span 2.8mm, IPC High Density)
footprint SOT23-5_M (SOT23, 5-Leads, Body 2.9x1.6mm, Pitch 0.95mm, Lead Span 2.8mm, IPC Low Density)
pins: 1 ~{RST} (out), 2 GND (power), 3 ~{MR} (in), 4 RST IN (in), 5 VCC (power)

## MAX6309UK48D4-T
designator U?
5-Pin, Multiple-Input, Programmable Reset IC
footprint SOT23-5_N (SOT23, 5-Leads, Body 2.9x1.6mm, Pitch 0.95mm, Lead Span 2.8mm, IPC Medium Density)
footprint SOT23-5_L (SOT23, 5-Leads, Body 2.9x1.6mm, Pitch 0.95mm, Lead Span 2.8mm, IPC High Density)
footprint SOT23-5_M (SOT23, 5-Leads, Body 2.9x1.6mm, Pitch 0.95mm, Lead Span 2.8mm, IPC Low Density)
pins: 1 ~{RST} (out), 2 GND (power), 3 ~{MR} (in), 4 RST IN (in), 5 VCC (power)

## MAX6309UK49D1-T
designator U?
5-Pin, Multiple-Input, Programmable Reset IC
footprint SOT23-5_N (SOT23, 5-Leads, Body 2.9x1.6mm, Pitch 0.95mm, Lead Span 2.8mm, IPC Medium Density)
footprint SOT23-5_L (SOT23, 5-Leads, Body 2.9x1.6mm, Pitch 0.95mm, Lead Span 2.8mm, IPC High Density)
footprint SOT23-5_M (SOT23, 5-Leads, Body 2.9x1.6mm, Pitch 0.95mm, Lead Span 2.8mm, IPC Low Density)
pins: 1 ~{RST} (out), 2 GND (power), 3 ~{MR} (in), 4 RST IN (in), 5 VCC (power)

## MAX6309UK49D2-T
designator U?
5-Pin, Multiple-Input, Programmable Reset IC
footprint SOT23-5_N (SOT23, 5-Leads, Body 2.9x1.6mm, Pitch 0.95mm, Lead Span 2.8mm, IPC Medium Density)
footprint SOT23-5_L (SOT23, 5-Leads, Body 2.9x1.6mm, Pitch 0.95mm, Lead Span 2.8mm, IPC High Density)
footprint SOT23-5_M (SOT23, 5-Leads, Body 2.9x1.6mm, Pitch 0.95mm, Lead Span 2.8mm, IPC Low Density)
pins: 1 ~{RST} (out), 2 GND (power), 3 ~{MR} (in), 4 RST IN (in), 5 VCC (power)

## MAX6309UK49D3-T
designator U?
5-Pin, Multiple-Input, Programmable Reset IC
footprint SOT23-5_N (SOT23, 5-Leads, Body 2.9x1.6mm, Pitch 0.95mm, Lead Span 2.8mm, IPC Medium Density)
footprint SOT23-5_L (SOT23, 5-Leads, Body 2.9x1.6mm, Pitch 0.95mm, Lead Span 2.8mm, IPC High Density)
footprint SOT23-5_M (SOT23, 5-Leads, Body 2.9x1.6mm, Pitch 0.95mm, Lead Span 2.8mm, IPC Low Density)
pins: 1 ~{RST} (out), 2 GND (power), 3 ~{MR} (in), 4 RST IN (in), 5 VCC (power)

## MAX6309UK49D4-T
designator U?
5-Pin, Multiple-Input, Programmable Reset IC
footprint SOT23-5_N (SOT23, 5-Leads, Body 2.9x1.6mm, Pitch 0.95mm, Lead Span 2.8mm, IPC Medium Density)
footprint SOT23-5_L (SOT23, 5-Leads, Body 2.9x1.6mm, Pitch 0.95mm, Lead Span 2.8mm, IPC High Density)
footprint SOT23-5_M (SOT23, 5-Leads, Body 2.9x1.6mm, Pitch 0.95mm, Lead Span 2.8mm, IPC Low Density)
pins: 1 ~{RST} (out), 2 GND (power), 3 ~{MR} (in), 4 RST IN (in), 5 VCC (power)

## MAX6309UK50D1-T
designator U?
5-Pin, Multiple-Input, Programmable Reset IC
footprint SOT23-5_N (SOT23, 5-Leads, Body 2.9x1.6mm, Pitch 0.95mm, Lead Span 2.8mm, IPC Medium Density)
footprint SOT23-5_L (SOT23, 5-Leads, Body 2.9x1.6mm, Pitch 0.95mm, Lead Span 2.8mm, IPC High Density)
footprint SOT23-5_M (SOT23, 5-Leads, Body 2.9x1.6mm, Pitch 0.95mm, Lead Span 2.8mm, IPC Low Density)
pins: 1 ~{RST} (out), 2 GND (power), 3 ~{MR} (in), 4 RST IN (in), 5 VCC (power)

## MAX6309UK50D2-T
designator U?
5-Pin, Multiple-Input, Programmable Reset IC
footprint SOT23-5_N (SOT23, 5-Leads, Body 2.9x1.6mm, Pitch 0.95mm, Lead Span 2.8mm, IPC Medium Density)
footprint SOT23-5_L (SOT23, 5-Leads, Body 2.9x1.6mm, Pitch 0.95mm, Lead Span 2.8mm, IPC High Density)
footprint SOT23-5_M (SOT23, 5-Leads, Body 2.9x1.6mm, Pitch 0.95mm, Lead Span 2.8mm, IPC Low Density)
pins: 1 ~{RST} (out), 2 GND (power), 3 ~{MR} (in), 4 RST IN (in), 5 VCC (power)

## MAX6309UK50D3-T
designator U?
5-Pin, Multiple-Input, Programmable Reset IC
footprint SOT23-5_N (SOT23, 5-Leads, Body 2.9x1.6mm, Pitch 0.95mm, Lead Span 2.8mm, IPC Medium Density)
footprint SOT23-5_L (SOT23, 5-Leads, Body 2.9x1.6mm, Pitch 0.95mm, Lead Span 2.8mm, IPC High Density)
footprint SOT23-5_M (SOT23, 5-Leads, Body 2.9x1.6mm, Pitch 0.95mm, Lead Span 2.8mm, IPC Low Density)
pins: 1 ~{RST} (out), 2 GND (power), 3 ~{MR} (in), 4 RST IN (in), 5 VCC (power)

## MAX6309UK50D4-T
designator U?
5-Pin, Multiple-Input, Programmable Reset IC
footprint SOT23-5_N (SOT23, 5-Leads, Body 2.9x1.6mm, Pitch 0.95mm, Lead Span 2.8mm, IPC Medium Density)
footprint SOT23-5_L (SOT23, 5-Leads, Body 2.9x1.6mm, Pitch 0.95mm, Lead Span 2.8mm, IPC High Density)
footprint SOT23-5_M (SOT23, 5-Leads, Body 2.9x1.6mm, Pitch 0.95mm, Lead Span 2.8mm, IPC Low Density)
pins: 1 ~{RST} (out), 2 GND (power), 3 ~{MR} (in), 4 RST IN (in), 5 VCC (power)

## MAX6310UK25D1-T
designator U?
5-Pin, Multiple-Input, Programmable Reset IC
footprint SOT23-5_N (SOT23, 5-Leads, Body 2.9x1.6mm, Pitch 0.95mm, Lead Span 2.8mm, IPC Medium Density)
footprint SOT23-5_L (SOT23, 5-Leads, Body 2.9x1.6mm, Pitch 0.95mm, Lead Span 2.8mm, IPC High Density)
footprint SOT23-5_M (SOT23, 5-Leads, Body 2.9x1.6mm, Pitch 0.95mm, Lead Span 2.8mm, IPC Low Density)
pins: 1 ~{RST} (out), 2 GND (power), 3 RST IN (in), 4 OVRST IN, 5 VCC (power)

## MAX6310UK25D2-T
designator U?
5-Pin, Multiple-Input, Programmable Reset IC
footprint SOT23-5_N (SOT23, 5-Leads, Body 2.9x1.6mm, Pitch 0.95mm, Lead Span 2.8mm, IPC Medium Density)
footprint SOT23-5_L (SOT23, 5-Leads, Body 2.9x1.6mm, Pitch 0.95mm, Lead Span 2.8mm, IPC High Density)
footprint SOT23-5_M (SOT23, 5-Leads, Body 2.9x1.6mm, Pitch 0.95mm, Lead Span 2.8mm, IPC Low Density)
pins: 1 ~{RST} (out), 2 GND (power), 3 RST IN (in), 4 OVRST IN, 5 VCC (power)

## MAX6310UK25D3-T
designator U?
5-Pin, Multiple-Input, Programmable Reset IC
footprint SOT23-5_N (SOT23, 5-Leads, Body 2.9x1.6mm, Pitch 0.95mm, Lead Span 2.8mm, IPC Medium Density)
footprint SOT23-5_L (SOT23, 5-Leads, Body 2.9x1.6mm, Pitch 0.95mm, Lead Span 2.8mm, IPC High Density)
footprint SOT23-5_M (SOT23, 5-Leads, Body 2.9x1.6mm, Pitch 0.95mm, Lead Span 2.8mm, IPC Low Density)
pins: 1 ~{RST} (out), 2 GND (power), 3 RST IN (in), 4 OVRST IN, 5 VCC (power)

## MAX6310UK25D4-T
designator U?
5-Pin, Multiple-Input, Programmable Reset IC
footprint SOT23-5_N (SOT23, 5-Leads, Body 2.9x1.6mm, Pitch 0.95mm, Lead Span 2.8mm, IPC Medium Density)
footprint SOT23-5_L (SOT23, 5-Leads, Body 2.9x1.6mm, Pitch 0.95mm, Lead Span 2.8mm, IPC High Density)
footprint SOT23-5_M (SOT23, 5-Leads, Body 2.9x1.6mm, Pitch 0.95mm, Lead Span 2.8mm, IPC Low Density)
pins: 1 ~{RST} (out), 2 GND (power), 3 RST IN (in), 4 OVRST IN, 5 VCC (power)

## MAX6310UK26D1-T
designator U?
5-Pin, Multiple-Input, Programmable Reset IC
footprint SOT23-5_N (SOT23, 5-Leads, Body 2.9x1.6mm, Pitch 0.95mm, Lead Span 2.8mm, IPC Medium Density)
footprint SOT23-5_L (SOT23, 5-Leads, Body 2.9x1.6mm, Pitch 0.95mm, Lead Span 2.8mm, IPC High Density)
footprint SOT23-5_M (SOT23, 5-Leads, Body 2.9x1.6mm, Pitch 0.95mm, Lead Span 2.8mm, IPC Low Density)
pins: 1 ~{RST} (out), 2 GND (power), 3 RST IN (in), 4 OVRST IN, 5 VCC (power)

## MAX6310UK26D2-T
designator U?
5-Pin, Multiple-Input, Programmable Reset IC
footprint SOT23-5_N (SOT23, 5-Leads, Body 2.9x1.6mm, Pitch 0.95mm, Lead Span 2.8mm, IPC Medium Density)
footprint SOT23-5_L (SOT23, 5-Leads, Body 2.9x1.6mm, Pitch 0.95mm, Lead Span 2.8mm, IPC High Density)
footprint SOT23-5_M (SOT23, 5-Leads, Body 2.9x1.6mm, Pitch 0.95mm, Lead Span 2.8mm, IPC Low Density)
pins: 1 ~{RST} (out), 2 GND (power), 3 RST IN (in), 4 OVRST IN, 5 VCC (power)

## MAX6310UK26D3-T
designator U?
5-Pin, Multiple-Input, Programmable Reset IC
footprint SOT23-5_N (SOT23, 5-Leads, Body 2.9x1.6mm, Pitch 0.95mm, Lead Span 2.8mm, IPC Medium Density)
footprint SOT23-5_L (SOT23, 5-Leads, Body 2.9x1.6mm, Pitch 0.95mm, Lead Span 2.8mm, IPC High Density)
footprint SOT23-5_M (SOT23, 5-Leads, Body 2.9x1.6mm, Pitch 0.95mm, Lead Span 2.8mm, IPC Low Density)
pins: 1 ~{RST} (out), 2 GND (power), 3 RST IN (in), 4 OVRST IN, 5 VCC (power)

## MAX6310UK26D4-T
designator U?
5-Pin, Multiple-Input, Programmable Reset IC
footprint SOT23-5_N (SOT23, 5-Leads, Body 2.9x1.6mm, Pitch 0.95mm, Lead Span 2.8mm, IPC Medium Density)
footprint SOT23-5_L (SOT23, 5-Leads, Body 2.9x1.6mm, Pitch 0.95mm, Lead Span 2.8mm, IPC High Density)
footprint SOT23-5_M (SOT23, 5-Leads, Body 2.9x1.6mm, Pitch 0.95mm, Lead Span 2.8mm, IPC Low Density)
pins: 1 ~{RST} (out), 2 GND (power), 3 RST IN (in), 4 OVRST IN, 5 VCC (power)

## MAX6310UK27D1-T
designator U?
5-Pin, Multiple-Input, Programmable Reset IC
footprint SOT23-5_N (SOT23, 5-Leads, Body 2.9x1.6mm, Pitch 0.95mm, Lead Span 2.8mm, IPC Medium Density)
footprint SOT23-5_L (SOT23, 5-Leads, Body 2.9x1.6mm, Pitch 0.95mm, Lead Span 2.8mm, IPC High Density)
footprint SOT23-5_M (SOT23, 5-Leads, Body 2.9x1.6mm, Pitch 0.95mm, Lead Span 2.8mm, IPC Low Density)
pins: 1 ~{RST} (out), 2 GND (power), 3 RST IN (in), 4 OVRST IN, 5 VCC (power)

## MAX6310UK27D2-T
designator U?
5-Pin, Multiple-Input, Programmable Reset IC
footprint SOT23-5_N (SOT23, 5-Leads, Body 2.9x1.6mm, Pitch 0.95mm, Lead Span 2.8mm, IPC Medium Density)
footprint SOT23-5_L (SOT23, 5-Leads, Body 2.9x1.6mm, Pitch 0.95mm, Lead Span 2.8mm, IPC High Density)
footprint SOT23-5_M (SOT23, 5-Leads, Body 2.9x1.6mm, Pitch 0.95mm, Lead Span 2.8mm, IPC Low Density)
pins: 1 ~{RST} (out), 2 GND (power), 3 RST IN (in), 4 OVRST IN, 5 VCC (power)

## MAX6310UK27D3-T
designator U?
5-Pin, Multiple-Input, Programmable Reset IC
footprint SOT23-5_N (SOT23, 5-Leads, Body 2.9x1.6mm, Pitch 0.95mm, Lead Span 2.8mm, IPC Medium Density)
footprint SOT23-5_L (SOT23, 5-Leads, Body 2.9x1.6mm, Pitch 0.95mm, Lead Span 2.8mm, IPC High Density)
footprint SOT23-5_M (SOT23, 5-Leads, Body 2.9x1.6mm, Pitch 0.95mm, Lead Span 2.8mm, IPC Low Density)
pins: 1 ~{RST} (out), 2 GND (power), 3 RST IN (in), 4 OVRST IN, 5 VCC (power)

## MAX6310UK27D4-T
designator U?
5-Pin, Multiple-Input, Programmable Reset IC
footprint SOT23-5_N (SOT23, 5-Leads, Body 2.9x1.6mm, Pitch 0.95mm, Lead Span 2.8mm, IPC Medium Density)
footprint SOT23-5_L (SOT23, 5-Leads, Body 2.9x1.6mm, Pitch 0.95mm, Lead Span 2.8mm, IPC High Density)
footprint SOT23-5_M (SOT23, 5-Leads, Body 2.9x1.6mm, Pitch 0.95mm, Lead Span 2.8mm, IPC Low Density)
pins: 1 ~{RST} (out), 2 GND (power), 3 RST IN (in), 4 OVRST IN, 5 VCC (power)

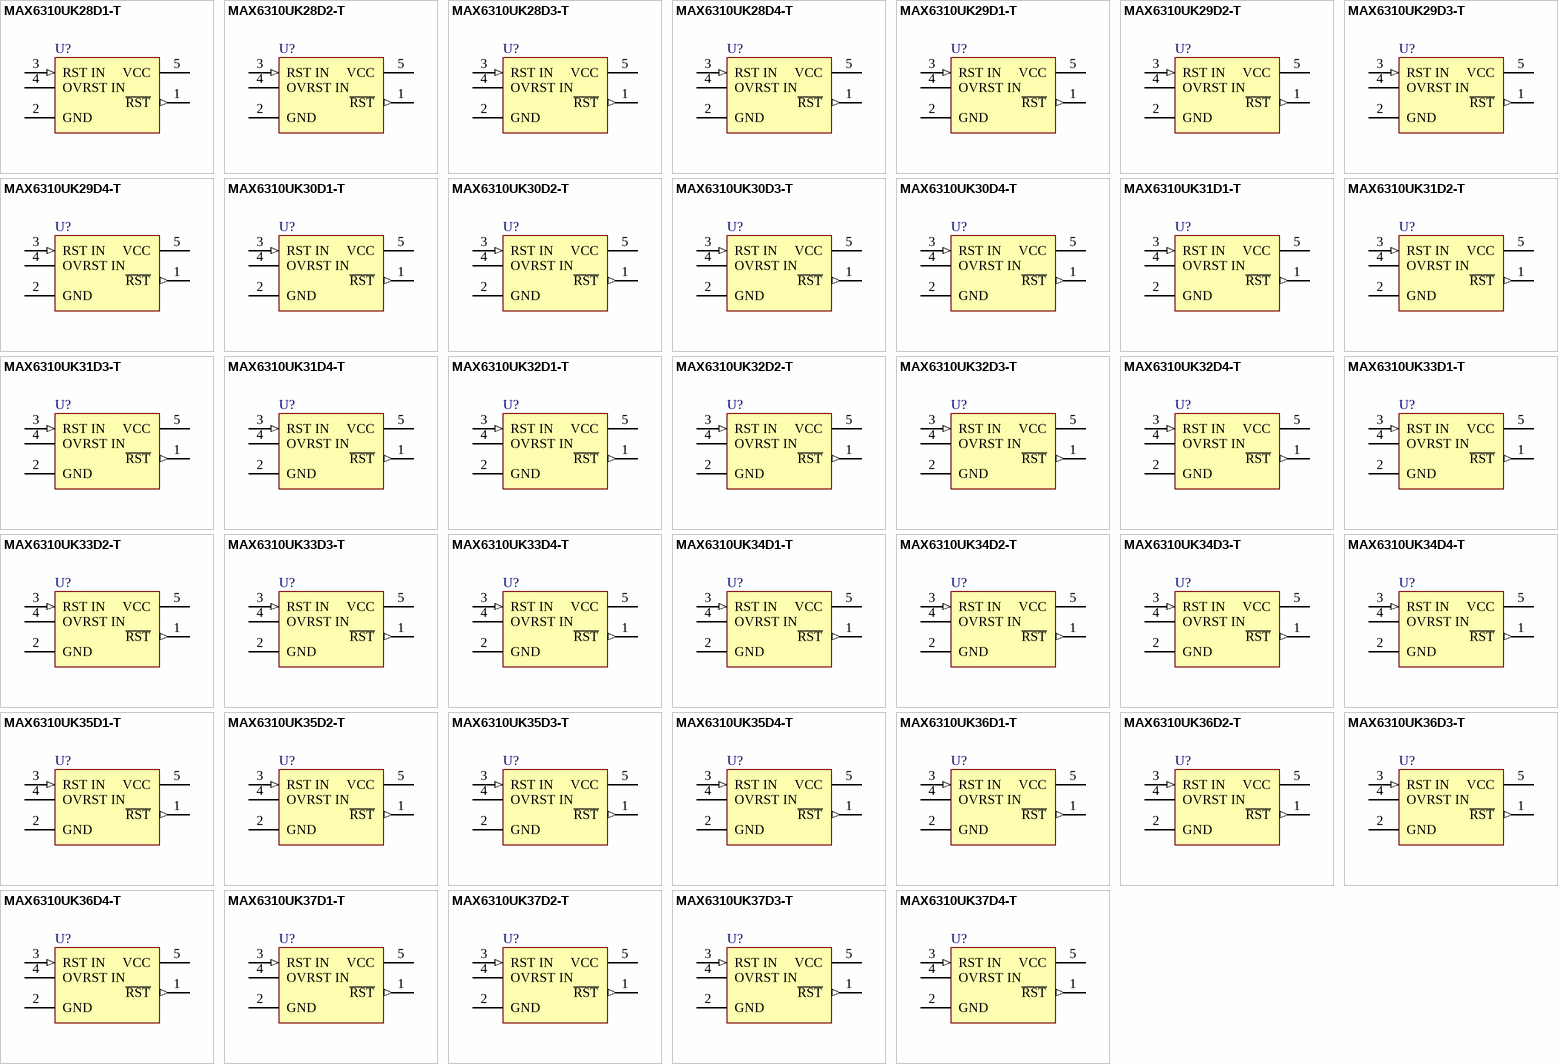
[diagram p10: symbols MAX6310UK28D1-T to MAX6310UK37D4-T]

## MAX6310UK28D1-T
designator U?
5-Pin, Multiple-Input, Programmable Reset IC
footprint SOT23-5_N (SOT23, 5-Leads, Body 2.9x1.6mm, Pitch 0.95mm, Lead Span 2.8mm, IPC Medium Density)
footprint SOT23-5_L (SOT23, 5-Leads, Body 2.9x1.6mm, Pitch 0.95mm, Lead Span 2.8mm, IPC High Density)
footprint SOT23-5_M (SOT23, 5-Leads, Body 2.9x1.6mm, Pitch 0.95mm, Lead Span 2.8mm, IPC Low Density)
pins: 1 ~{RST} (out), 2 GND (power), 3 RST IN (in), 4 OVRST IN, 5 VCC (power)

## MAX6310UK28D2-T
designator U?
5-Pin, Multiple-Input, Programmable Reset IC
footprint SOT23-5_N (SOT23, 5-Leads, Body 2.9x1.6mm, Pitch 0.95mm, Lead Span 2.8mm, IPC Medium Density)
footprint SOT23-5_L (SOT23, 5-Leads, Body 2.9x1.6mm, Pitch 0.95mm, Lead Span 2.8mm, IPC High Density)
footprint SOT23-5_M (SOT23, 5-Leads, Body 2.9x1.6mm, Pitch 0.95mm, Lead Span 2.8mm, IPC Low Density)
pins: 1 ~{RST} (out), 2 GND (power), 3 RST IN (in), 4 OVRST IN, 5 VCC (power)

## MAX6310UK28D3-T
designator U?
5-Pin, Multiple-Input, Programmable Reset IC
footprint SOT23-5_N (SOT23, 5-Leads, Body 2.9x1.6mm, Pitch 0.95mm, Lead Span 2.8mm, IPC Medium Density)
footprint SOT23-5_L (SOT23, 5-Leads, Body 2.9x1.6mm, Pitch 0.95mm, Lead Span 2.8mm, IPC High Density)
footprint SOT23-5_M (SOT23, 5-Leads, Body 2.9x1.6mm, Pitch 0.95mm, Lead Span 2.8mm, IPC Low Density)
pins: 1 ~{RST} (out), 2 GND (power), 3 RST IN (in), 4 OVRST IN, 5 VCC (power)

## MAX6310UK28D4-T
designator U?
5-Pin, Multiple-Input, Programmable Reset IC
footprint SOT23-5_N (SOT23, 5-Leads, Body 2.9x1.6mm, Pitch 0.95mm, Lead Span 2.8mm, IPC Medium Density)
footprint SOT23-5_L (SOT23, 5-Leads, Body 2.9x1.6mm, Pitch 0.95mm, Lead Span 2.8mm, IPC High Density)
footprint SOT23-5_M (SOT23, 5-Leads, Body 2.9x1.6mm, Pitch 0.95mm, Lead Span 2.8mm, IPC Low Density)
pins: 1 ~{RST} (out), 2 GND (power), 3 RST IN (in), 4 OVRST IN, 5 VCC (power)

## MAX6310UK29D1-T
designator U?
5-Pin, Multiple-Input, Programmable Reset IC
footprint SOT23-5_N (SOT23, 5-Leads, Body 2.9x1.6mm, Pitch 0.95mm, Lead Span 2.8mm, IPC Medium Density)
footprint SOT23-5_L (SOT23, 5-Leads, Body 2.9x1.6mm, Pitch 0.95mm, Lead Span 2.8mm, IPC High Density)
footprint SOT23-5_M (SOT23, 5-Leads, Body 2.9x1.6mm, Pitch 0.95mm, Lead Span 2.8mm, IPC Low Density)
pins: 1 ~{RST} (out), 2 GND (power), 3 RST IN (in), 4 OVRST IN, 5 VCC (power)

## MAX6310UK29D2-T
designator U?
5-Pin, Multiple-Input, Programmable Reset IC
footprint SOT23-5_N (SOT23, 5-Leads, Body 2.9x1.6mm, Pitch 0.95mm, Lead Span 2.8mm, IPC Medium Density)
footprint SOT23-5_L (SOT23, 5-Leads, Body 2.9x1.6mm, Pitch 0.95mm, Lead Span 2.8mm, IPC High Density)
footprint SOT23-5_M (SOT23, 5-Leads, Body 2.9x1.6mm, Pitch 0.95mm, Lead Span 2.8mm, IPC Low Density)
pins: 1 ~{RST} (out), 2 GND (power), 3 RST IN (in), 4 OVRST IN, 5 VCC (power)

## MAX6310UK29D3-T
designator U?
5-Pin, Multiple-Input, Programmable Reset IC
footprint SOT23-5_N (SOT23, 5-Leads, Body 2.9x1.6mm, Pitch 0.95mm, Lead Span 2.8mm, IPC Medium Density)
footprint SOT23-5_L (SOT23, 5-Leads, Body 2.9x1.6mm, Pitch 0.95mm, Lead Span 2.8mm, IPC High Density)
footprint SOT23-5_M (SOT23, 5-Leads, Body 2.9x1.6mm, Pitch 0.95mm, Lead Span 2.8mm, IPC Low Density)
pins: 1 ~{RST} (out), 2 GND (power), 3 RST IN (in), 4 OVRST IN, 5 VCC (power)

## MAX6310UK29D4-T
designator U?
5-Pin, Multiple-Input, Programmable Reset IC
footprint SOT23-5_N (SOT23, 5-Leads, Body 2.9x1.6mm, Pitch 0.95mm, Lead Span 2.8mm, IPC Medium Density)
footprint SOT23-5_L (SOT23, 5-Leads, Body 2.9x1.6mm, Pitch 0.95mm, Lead Span 2.8mm, IPC High Density)
footprint SOT23-5_M (SOT23, 5-Leads, Body 2.9x1.6mm, Pitch 0.95mm, Lead Span 2.8mm, IPC Low Density)
pins: 1 ~{RST} (out), 2 GND (power), 3 RST IN (in), 4 OVRST IN, 5 VCC (power)

## MAX6310UK30D1-T
designator U?
5-Pin, Multiple-Input, Programmable Reset IC
footprint SOT23-5_N (SOT23, 5-Leads, Body 2.9x1.6mm, Pitch 0.95mm, Lead Span 2.8mm, IPC Medium Density)
footprint SOT23-5_L (SOT23, 5-Leads, Body 2.9x1.6mm, Pitch 0.95mm, Lead Span 2.8mm, IPC High Density)
footprint SOT23-5_M (SOT23, 5-Leads, Body 2.9x1.6mm, Pitch 0.95mm, Lead Span 2.8mm, IPC Low Density)
pins: 1 ~{RST} (out), 2 GND (power), 3 RST IN (in), 4 OVRST IN, 5 VCC (power)

## MAX6310UK30D2-T
designator U?
5-Pin, Multiple-Input, Programmable Reset IC
footprint SOT23-5_N (SOT23, 5-Leads, Body 2.9x1.6mm, Pitch 0.95mm, Lead Span 2.8mm, IPC Medium Density)
footprint SOT23-5_L (SOT23, 5-Leads, Body 2.9x1.6mm, Pitch 0.95mm, Lead Span 2.8mm, IPC High Density)
footprint SOT23-5_M (SOT23, 5-Leads, Body 2.9x1.6mm, Pitch 0.95mm, Lead Span 2.8mm, IPC Low Density)
pins: 1 ~{RST} (out), 2 GND (power), 3 RST IN (in), 4 OVRST IN, 5 VCC (power)

## MAX6310UK30D3-T
designator U?
5-Pin, Multiple-Input, Programmable Reset IC
footprint SOT23-5_N (SOT23, 5-Leads, Body 2.9x1.6mm, Pitch 0.95mm, Lead Span 2.8mm, IPC Medium Density)
footprint SOT23-5_L (SOT23, 5-Leads, Body 2.9x1.6mm, Pitch 0.95mm, Lead Span 2.8mm, IPC High Density)
footprint SOT23-5_M (SOT23, 5-Leads, Body 2.9x1.6mm, Pitch 0.95mm, Lead Span 2.8mm, IPC Low Density)
pins: 1 ~{RST} (out), 2 GND (power), 3 RST IN (in), 4 OVRST IN, 5 VCC (power)

## MAX6310UK30D4-T
designator U?
5-Pin, Multiple-Input, Programmable Reset IC
footprint SOT23-5_N (SOT23, 5-Leads, Body 2.9x1.6mm, Pitch 0.95mm, Lead Span 2.8mm, IPC Medium Density)
footprint SOT23-5_L (SOT23, 5-Leads, Body 2.9x1.6mm, Pitch 0.95mm, Lead Span 2.8mm, IPC High Density)
footprint SOT23-5_M (SOT23, 5-Leads, Body 2.9x1.6mm, Pitch 0.95mm, Lead Span 2.8mm, IPC Low Density)
pins: 1 ~{RST} (out), 2 GND (power), 3 RST IN (in), 4 OVRST IN, 5 VCC (power)

## MAX6310UK31D1-T
designator U?
5-Pin, Multiple-Input, Programmable Reset IC
footprint SOT23-5_N (SOT23, 5-Leads, Body 2.9x1.6mm, Pitch 0.95mm, Lead Span 2.8mm, IPC Medium Density)
footprint SOT23-5_L (SOT23, 5-Leads, Body 2.9x1.6mm, Pitch 0.95mm, Lead Span 2.8mm, IPC High Density)
footprint SOT23-5_M (SOT23, 5-Leads, Body 2.9x1.6mm, Pitch 0.95mm, Lead Span 2.8mm, IPC Low Density)
pins: 1 ~{RST} (out), 2 GND (power), 3 RST IN (in), 4 OVRST IN, 5 VCC (power)

## MAX6310UK31D2-T
designator U?
5-Pin, Multiple-Input, Programmable Reset IC
footprint SOT23-5_N (SOT23, 5-Leads, Body 2.9x1.6mm, Pitch 0.95mm, Lead Span 2.8mm, IPC Medium Density)
footprint SOT23-5_L (SOT23, 5-Leads, Body 2.9x1.6mm, Pitch 0.95mm, Lead Span 2.8mm, IPC High Density)
footprint SOT23-5_M (SOT23, 5-Leads, Body 2.9x1.6mm, Pitch 0.95mm, Lead Span 2.8mm, IPC Low Density)
pins: 1 ~{RST} (out), 2 GND (power), 3 RST IN (in), 4 OVRST IN, 5 VCC (power)

## MAX6310UK31D3-T
designator U?
5-Pin, Multiple-Input, Programmable Reset IC
footprint SOT23-5_N (SOT23, 5-Leads, Body 2.9x1.6mm, Pitch 0.95mm, Lead Span 2.8mm, IPC Medium Density)
footprint SOT23-5_L (SOT23, 5-Leads, Body 2.9x1.6mm, Pitch 0.95mm, Lead Span 2.8mm, IPC High Density)
footprint SOT23-5_M (SOT23, 5-Leads, Body 2.9x1.6mm, Pitch 0.95mm, Lead Span 2.8mm, IPC Low Density)
pins: 1 ~{RST} (out), 2 GND (power), 3 RST IN (in), 4 OVRST IN, 5 VCC (power)

## MAX6310UK31D4-T
designator U?
5-Pin, Multiple-Input, Programmable Reset IC
footprint SOT23-5_N (SOT23, 5-Leads, Body 2.9x1.6mm, Pitch 0.95mm, Lead Span 2.8mm, IPC Medium Density)
footprint SOT23-5_L (SOT23, 5-Leads, Body 2.9x1.6mm, Pitch 0.95mm, Lead Span 2.8mm, IPC High Density)
footprint SOT23-5_M (SOT23, 5-Leads, Body 2.9x1.6mm, Pitch 0.95mm, Lead Span 2.8mm, IPC Low Density)
pins: 1 ~{RST} (out), 2 GND (power), 3 RST IN (in), 4 OVRST IN, 5 VCC (power)

## MAX6310UK32D1-T
designator U?
5-Pin, Multiple-Input, Programmable Reset IC
footprint SOT23-5_N (SOT23, 5-Leads, Body 2.9x1.6mm, Pitch 0.95mm, Lead Span 2.8mm, IPC Medium Density)
footprint SOT23-5_L (SOT23, 5-Leads, Body 2.9x1.6mm, Pitch 0.95mm, Lead Span 2.8mm, IPC High Density)
footprint SOT23-5_M (SOT23, 5-Leads, Body 2.9x1.6mm, Pitch 0.95mm, Lead Span 2.8mm, IPC Low Density)
pins: 1 ~{RST} (out), 2 GND (power), 3 RST IN (in), 4 OVRST IN, 5 VCC (power)

## MAX6310UK32D2-T
designator U?
5-Pin, Multiple-Input, Programmable Reset IC
footprint SOT23-5_N (SOT23, 5-Leads, Body 2.9x1.6mm, Pitch 0.95mm, Lead Span 2.8mm, IPC Medium Density)
footprint SOT23-5_L (SOT23, 5-Leads, Body 2.9x1.6mm, Pitch 0.95mm, Lead Span 2.8mm, IPC High Density)
footprint SOT23-5_M (SOT23, 5-Leads, Body 2.9x1.6mm, Pitch 0.95mm, Lead Span 2.8mm, IPC Low Density)
pins: 1 ~{RST} (out), 2 GND (power), 3 RST IN (in), 4 OVRST IN, 5 VCC (power)

## MAX6310UK32D3-T
designator U?
5-Pin, Multiple-Input, Programmable Reset IC
footprint SOT23-5_N (SOT23, 5-Leads, Body 2.9x1.6mm, Pitch 0.95mm, Lead Span 2.8mm, IPC Medium Density)
footprint SOT23-5_L (SOT23, 5-Leads, Body 2.9x1.6mm, Pitch 0.95mm, Lead Span 2.8mm, IPC High Density)
footprint SOT23-5_M (SOT23, 5-Leads, Body 2.9x1.6mm, Pitch 0.95mm, Lead Span 2.8mm, IPC Low Density)
pins: 1 ~{RST} (out), 2 GND (power), 3 RST IN (in), 4 OVRST IN, 5 VCC (power)

## MAX6310UK32D4-T
designator U?
5-Pin, Multiple-Input, Programmable Reset IC
footprint SOT23-5_N (SOT23, 5-Leads, Body 2.9x1.6mm, Pitch 0.95mm, Lead Span 2.8mm, IPC Medium Density)
footprint SOT23-5_L (SOT23, 5-Leads, Body 2.9x1.6mm, Pitch 0.95mm, Lead Span 2.8mm, IPC High Density)
footprint SOT23-5_M (SOT23, 5-Leads, Body 2.9x1.6mm, Pitch 0.95mm, Lead Span 2.8mm, IPC Low Density)
pins: 1 ~{RST} (out), 2 GND (power), 3 RST IN (in), 4 OVRST IN, 5 VCC (power)

## MAX6310UK33D1-T
designator U?
5-Pin, Multiple-Input, Programmable Reset IC
footprint SOT23-5_N (SOT23, 5-Leads, Body 2.9x1.6mm, Pitch 0.95mm, Lead Span 2.8mm, IPC Medium Density)
footprint SOT23-5_L (SOT23, 5-Leads, Body 2.9x1.6mm, Pitch 0.95mm, Lead Span 2.8mm, IPC High Density)
footprint SOT23-5_M (SOT23, 5-Leads, Body 2.9x1.6mm, Pitch 0.95mm, Lead Span 2.8mm, IPC Low Density)
pins: 1 ~{RST} (out), 2 GND (power), 3 RST IN (in), 4 OVRST IN, 5 VCC (power)

## MAX6310UK33D2-T
designator U?
5-Pin, Multiple-Input, Programmable Reset IC
footprint SOT23-5_N (SOT23, 5-Leads, Body 2.9x1.6mm, Pitch 0.95mm, Lead Span 2.8mm, IPC Medium Density)
footprint SOT23-5_L (SOT23, 5-Leads, Body 2.9x1.6mm, Pitch 0.95mm, Lead Span 2.8mm, IPC High Density)
footprint SOT23-5_M (SOT23, 5-Leads, Body 2.9x1.6mm, Pitch 0.95mm, Lead Span 2.8mm, IPC Low Density)
pins: 1 ~{RST} (out), 2 GND (power), 3 RST IN (in), 4 OVRST IN, 5 VCC (power)

## MAX6310UK33D3-T
designator U?
5-Pin, Multiple-Input, Programmable Reset IC
footprint SOT23-5_N (SOT23, 5-Leads, Body 2.9x1.6mm, Pitch 0.95mm, Lead Span 2.8mm, IPC Medium Density)
footprint SOT23-5_L (SOT23, 5-Leads, Body 2.9x1.6mm, Pitch 0.95mm, Lead Span 2.8mm, IPC High Density)
footprint SOT23-5_M (SOT23, 5-Leads, Body 2.9x1.6mm, Pitch 0.95mm, Lead Span 2.8mm, IPC Low Density)
pins: 1 ~{RST} (out), 2 GND (power), 3 RST IN (in), 4 OVRST IN, 5 VCC (power)

## MAX6310UK33D4-T
designator U?
5-Pin, Multiple-Input, Programmable Reset IC
footprint SOT23-5_N (SOT23, 5-Leads, Body 2.9x1.6mm, Pitch 0.95mm, Lead Span 2.8mm, IPC Medium Density)
footprint SOT23-5_L (SOT23, 5-Leads, Body 2.9x1.6mm, Pitch 0.95mm, Lead Span 2.8mm, IPC High Density)
footprint SOT23-5_M (SOT23, 5-Leads, Body 2.9x1.6mm, Pitch 0.95mm, Lead Span 2.8mm, IPC Low Density)
pins: 1 ~{RST} (out), 2 GND (power), 3 RST IN (in), 4 OVRST IN, 5 VCC (power)

## MAX6310UK34D1-T
designator U?
5-Pin, Multiple-Input, Programmable Reset IC
footprint SOT23-5_N (SOT23, 5-Leads, Body 2.9x1.6mm, Pitch 0.95mm, Lead Span 2.8mm, IPC Medium Density)
footprint SOT23-5_L (SOT23, 5-Leads, Body 2.9x1.6mm, Pitch 0.95mm, Lead Span 2.8mm, IPC High Density)
footprint SOT23-5_M (SOT23, 5-Leads, Body 2.9x1.6mm, Pitch 0.95mm, Lead Span 2.8mm, IPC Low Density)
pins: 1 ~{RST} (out), 2 GND (power), 3 RST IN (in), 4 OVRST IN, 5 VCC (power)

## MAX6310UK34D2-T
designator U?
5-Pin, Multiple-Input, Programmable Reset IC
footprint SOT23-5_N (SOT23, 5-Leads, Body 2.9x1.6mm, Pitch 0.95mm, Lead Span 2.8mm, IPC Medium Density)
footprint SOT23-5_L (SOT23, 5-Leads, Body 2.9x1.6mm, Pitch 0.95mm, Lead Span 2.8mm, IPC High Density)
footprint SOT23-5_M (SOT23, 5-Leads, Body 2.9x1.6mm, Pitch 0.95mm, Lead Span 2.8mm, IPC Low Density)
pins: 1 ~{RST} (out), 2 GND (power), 3 RST IN (in), 4 OVRST IN, 5 VCC (power)

## MAX6310UK34D3-T
designator U?
5-Pin, Multiple-Input, Programmable Reset IC
footprint SOT23-5_N (SOT23, 5-Leads, Body 2.9x1.6mm, Pitch 0.95mm, Lead Span 2.8mm, IPC Medium Density)
footprint SOT23-5_L (SOT23, 5-Leads, Body 2.9x1.6mm, Pitch 0.95mm, Lead Span 2.8mm, IPC High Density)
footprint SOT23-5_M (SOT23, 5-Leads, Body 2.9x1.6mm, Pitch 0.95mm, Lead Span 2.8mm, IPC Low Density)
pins: 1 ~{RST} (out), 2 GND (power), 3 RST IN (in), 4 OVRST IN, 5 VCC (power)

## MAX6310UK34D4-T
designator U?
5-Pin, Multiple-Input, Programmable Reset IC
footprint SOT23-5_N (SOT23, 5-Leads, Body 2.9x1.6mm, Pitch 0.95mm, Lead Span 2.8mm, IPC Medium Density)
footprint SOT23-5_L (SOT23, 5-Leads, Body 2.9x1.6mm, Pitch 0.95mm, Lead Span 2.8mm, IPC High Density)
footprint SOT23-5_M (SOT23, 5-Leads, Body 2.9x1.6mm, Pitch 0.95mm, Lead Span 2.8mm, IPC Low Density)
pins: 1 ~{RST} (out), 2 GND (power), 3 RST IN (in), 4 OVRST IN, 5 VCC (power)

## MAX6310UK35D1-T
designator U?
5-Pin, Multiple-Input, Programmable Reset IC
footprint SOT23-5_N (SOT23, 5-Leads, Body 2.9x1.6mm, Pitch 0.95mm, Lead Span 2.8mm, IPC Medium Density)
footprint SOT23-5_L (SOT23, 5-Leads, Body 2.9x1.6mm, Pitch 0.95mm, Lead Span 2.8mm, IPC High Density)
footprint SOT23-5_M (SOT23, 5-Leads, Body 2.9x1.6mm, Pitch 0.95mm, Lead Span 2.8mm, IPC Low Density)
pins: 1 ~{RST} (out), 2 GND (power), 3 RST IN (in), 4 OVRST IN, 5 VCC (power)

## MAX6310UK35D2-T
designator U?
5-Pin, Multiple-Input, Programmable Reset IC
footprint SOT23-5_N (SOT23, 5-Leads, Body 2.9x1.6mm, Pitch 0.95mm, Lead Span 2.8mm, IPC Medium Density)
footprint SOT23-5_L (SOT23, 5-Leads, Body 2.9x1.6mm, Pitch 0.95mm, Lead Span 2.8mm, IPC High Density)
footprint SOT23-5_M (SOT23, 5-Leads, Body 2.9x1.6mm, Pitch 0.95mm, Lead Span 2.8mm, IPC Low Density)
pins: 1 ~{RST} (out), 2 GND (power), 3 RST IN (in), 4 OVRST IN, 5 VCC (power)

## MAX6310UK35D3-T
designator U?
5-Pin, Multiple-Input, Programmable Reset IC
footprint SOT23-5_N (SOT23, 5-Leads, Body 2.9x1.6mm, Pitch 0.95mm, Lead Span 2.8mm, IPC Medium Density)
footprint SOT23-5_L (SOT23, 5-Leads, Body 2.9x1.6mm, Pitch 0.95mm, Lead Span 2.8mm, IPC High Density)
footprint SOT23-5_M (SOT23, 5-Leads, Body 2.9x1.6mm, Pitch 0.95mm, Lead Span 2.8mm, IPC Low Density)
pins: 1 ~{RST} (out), 2 GND (power), 3 RST IN (in), 4 OVRST IN, 5 VCC (power)

## MAX6310UK35D4-T
designator U?
5-Pin, Multiple-Input, Programmable Reset IC
footprint SOT23-5_N (SOT23, 5-Leads, Body 2.9x1.6mm, Pitch 0.95mm, Lead Span 2.8mm, IPC Medium Density)
footprint SOT23-5_L (SOT23, 5-Leads, Body 2.9x1.6mm, Pitch 0.95mm, Lead Span 2.8mm, IPC High Density)
footprint SOT23-5_M (SOT23, 5-Leads, Body 2.9x1.6mm, Pitch 0.95mm, Lead Span 2.8mm, IPC Low Density)
pins: 1 ~{RST} (out), 2 GND (power), 3 RST IN (in), 4 OVRST IN, 5 VCC (power)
